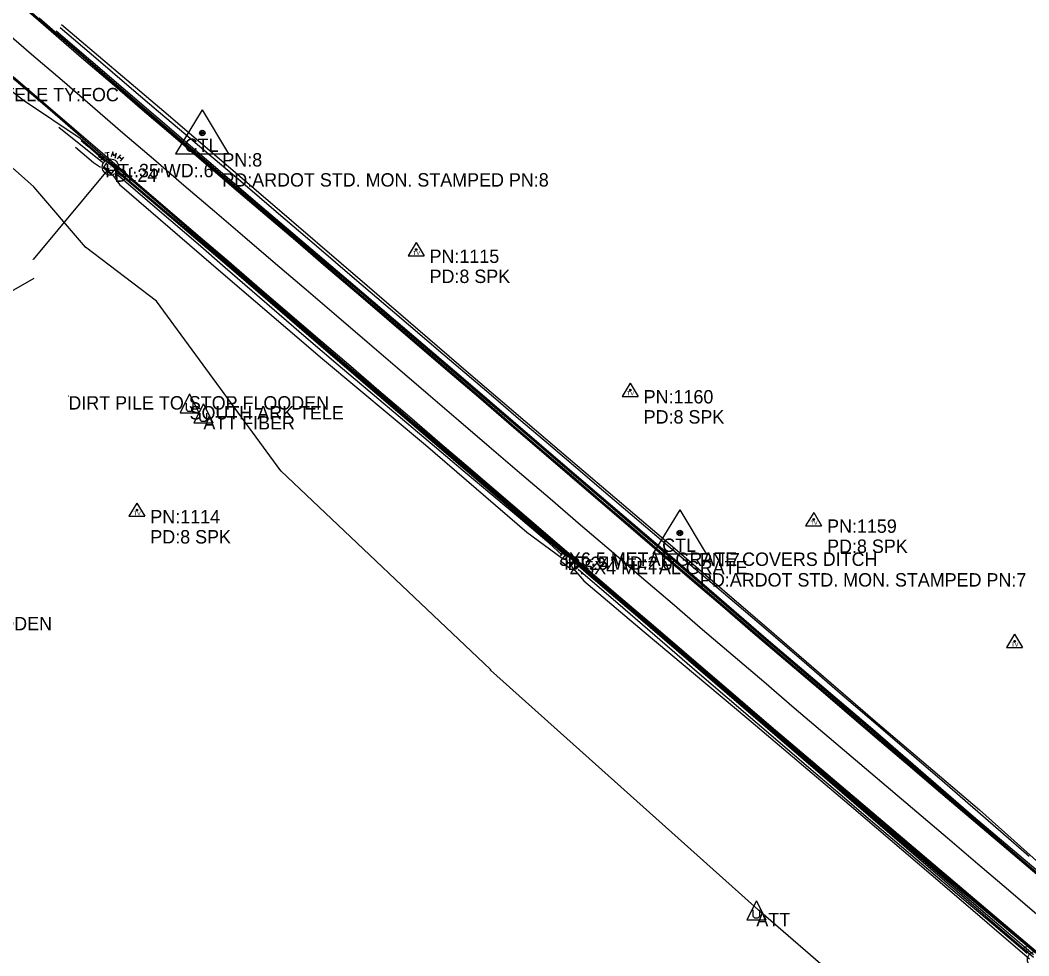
# Model space of a CAD drawing. Extents: x 878399 to 889864, y 1564003 to 1567413.
# Drawn here: x 884308.5 to 884685, y 1565532.7 to 1565882 of the extents above; entities that cross this region are included whole.
import ezdxf

# ---------------------------------------------------------------- set-up
doc = ezdxf.new("R2010")
doc.units = 0
for name, color, linetype in [('S_CATCH_BASIN_ANNOT', 7, 'Continuous'), ('S_DITCHLINE', 7, 'Continuous'), ('S_DRG_PT_SYM', 7, 'Continuous'), ('S_DROP_INLET_ANNOT', 7, 'Continuous'), ('S_EDGE_CONCRETE', 7, 'Continuous'), ('S_EDGE_PAVEMENT', 7, 'Continuous'), ('S_FIBER_OPTIC_CABLE', 7, 'Continuous'), ('S_MSC_PT_SYM', 7, 'Continuous'), ('S_PAVEMENT_CROWN', 7, 'Continuous'), ('S_PRIMARY_CTL', 7, 'Continuous'), ('S_PRIMARY_CTL_ANNOT', 7, 'Continuous'), ('S_SECONDARY_CTL', 7, 'Continuous'), ('S_SECONDARY_CTL_ANNOT', 7, 'Continuous'), ('S_SHOULDER', 7, 'Continuous'), ('S_STORM_SEWER', 7, 'Continuous'), ('S_STORM_SEWER_ANNOT', 7, 'Continuous'), ('S_SURVEY_TEXT_ANNOT', 7, 'Continuous'), ('S_UTILITY_POLE', 7, 'Continuous'), ('S_UTILITY_POLE_ANNOT', 7, 'Continuous'), ('S_UTL_PT_SYM', 7, 'Continuous')]:
    doc.layers.add(name, color=color, linetype=linetype)

msp = doc.modelspace()

# ---------------------------------------------------------------- linework, layer by layer
at = {"layer": 'S_DITCHLINE'}
for points in [[(884685.15, 1565569.81), (884674.64, 1565578.91), (884664.13, 1565588), (884653.63, 1565597.1), (884643.12, 1565606.2), (884628.83, 1565618.48), (884614.53, 1565630.77), (884600.24, 1565643.05), (884585.94, 1565655.34), (884571.02, 1565668.05), (884556.1, 1565680.77), (884541.18, 1565693.48), (884526.26, 1565706.2), (884515.97, 1565714.94), (884505.68, 1565723.69), (884495.4, 1565732.44), (884485.11, 1565741.19), (884466.28, 1565757.28), (884447.44, 1565773.36), (884433.25, 1565785.49), (884419.07, 1565797.62), (884404.88, 1565809.75), (884390.7, 1565821.88), (884380.52, 1565830.51), (884370.34, 1565839.14), (884360.16, 1565847.77), (884349.98, 1565856.41), (884336.68, 1565867.8), (884323.39, 1565879.2)], [(884339.24, 1565828.92), (884322.91, 1565841.99)], [(884510.8, 1565682.24), (884505.96, 1565686.8), (884495.25, 1565695.8), (884484.53, 1565704.79), (884473.82, 1565713.78), (884463.1, 1565722.78), (884451.14, 1565732.92), (884439.18, 1565743.06), (884427.22, 1565753.2), (884415.26, 1565763.35), (884405.17, 1565772.09), (884395.09, 1565780.83), (884385.01, 1565789.58), (884374.93, 1565798.32), (884359.6, 1565811.48), (884344.27, 1565824.65)], [(884313.57, 1565785.57), (884298.88, 1565777.18), (884284.19, 1565768.8), (884269.5, 1565760.41), (884254.81, 1565752.03), (884236.66, 1565741.86), (884218.52, 1565731.69), (884200.38, 1565721.52), (884182.24, 1565711.35), (884162.67, 1565700.67), (884143.1, 1565689.99), (884123.52, 1565679.31), (884103.95, 1565668.64), (884086.69, 1565660), (884069.42, 1565651.36), (884052.15, 1565642.72), (884034.89, 1565634.08)], [(884684.4, 1565533.51), (884671.82, 1565544.18), (884659.24, 1565554.85), (884646.66, 1565565.51), (884634.08, 1565576.18), (884624.26, 1565584.58), (884614.45, 1565592.98), (884604.64, 1565601.38), (884594.82, 1565609.77), (884583.62, 1565619.39), (884572.43, 1565629.01), (884561.23, 1565638.62), (884550.03, 1565648.24), (884533.4, 1565662.59), (884516.78, 1565676.95)]]:
    msp.add_lwpolyline(points, dxfattribs=at)
at = {"layer": 'S_DRG_PT_SYM'}
for points in [[(884340.18, 1565828.36), (884340.18, 1565828.41), (884340.18, 1565828.36), (884340.13, 1565828.36), (884340.18, 1565828.36), (884340.18, 1565828.31), (884340.18, 1565828.36), (884340.23, 1565828.36)], [(884509.62, 1565683.26), (884509.62, 1565683.31), (884509.62, 1565683.26), (884509.57, 1565683.26), (884509.62, 1565683.26), (884509.62, 1565683.21), (884509.62, 1565683.26), (884509.67, 1565683.26)], [(884511.51, 1565681.81), (884511.51, 1565681.86), (884511.51, 1565681.81), (884511.46, 1565681.81), (884511.51, 1565681.81), (884511.51, 1565681.76), (884511.51, 1565681.81), (884511.56, 1565681.81)], [(884513.49, 1565680.14), (884513.49, 1565680.19), (884513.49, 1565680.14), (884513.44, 1565680.14), (884513.49, 1565680.14), (884513.49, 1565680.09), (884513.49, 1565680.14), (884513.54, 1565680.14)]]:
    msp.add_lwpolyline(points, dxfattribs=at)
at = {"layer": 'S_EDGE_CONCRETE'}
for points in [[(884321.95, 1565878.07), (884359.86, 1565845.48), (884397.91, 1565812.97), (884436.05, 1565780.63), (884473.97, 1565748.16), (884511.98, 1565715.58), (884549.99, 1565683.11), (884587.82, 1565650.46), (884625.88, 1565618.07), (884664.43, 1565584.66), (884703.02, 1565551.9)], [(884323.93, 1565880.39), (884362.03, 1565848.01), (884400.08, 1565815.49), (884438.03, 1565782.92), (884475.84, 1565750.35), (884513.92, 1565717.85), (884552.01, 1565685.45), (884589.9, 1565652.9), (884627.72, 1565620.23), (884666.58, 1565587.18), (884704.34, 1565553.44)], [(884331.19, 1565837.05), (884333.69, 1565834.93), (884337.93, 1565831.28), (884340.31, 1565829.21)], [(884329.11, 1565834.63), (884331.61, 1565832.51), (884335.89, 1565828.9), (884338.5, 1565827.11)], [(884344.06, 1565825.6), (884347.53, 1565823.02), (884385.57, 1565790.66), (884423.49, 1565758.06), (884461.52, 1565725.46), (884499.46, 1565692.99), (884511.84, 1565682.36)], [(884342.93, 1565824.29), (884345.52, 1565820.67), (884383.37, 1565788.1), (884421.31, 1565755.54), (884459.79, 1565723.43), (884497.65, 1565690.88), (884510.78, 1565681.13)], [(884514.23, 1565678.05), (884518.85, 1565672.72), (884541.36, 1565653.58), (884579.74, 1565621.54), (884617.9, 1565589.19), (884653.7, 1565558.74), (884685.33, 1565531.53)], [(884515.49, 1565679.51), (884520.78, 1565674.96), (884543.23, 1565655.78), (884581.22, 1565623.28), (884619.31, 1565590.84), (884655, 1565560.28), (884686.74, 1565533.19)]]:
    msp.add_lwpolyline(points, dxfattribs=at)
for points in [[(884344.03, 1565826.49), (884340.96, 1565829.03), (884339.39, 1565827.05), (884342.45, 1565824.52)], [(884342.53, 1565824.71), (884344.23, 1565826.64), (884341.27, 1565829.1), (884339.68, 1565827.32)], [(884512.15, 1565682.46), (884510.24, 1565680.17), (884513.52, 1565677.51), (884515.47, 1565679.77)]]:
    msp.add_lwpolyline(points, close=True, dxfattribs=at)
at = {"layer": 'S_EDGE_PAVEMENT'}
for points in [[(884308.74, 1565887.7), (884320.04, 1565877.9), (884331.41, 1565868.12), (884342.79, 1565858.35), (884354.16, 1565848.57), (884365.56, 1565838.81), (884376.99, 1565829.04), (884388.4, 1565819.3), (884399.81, 1565809.56), (884411.21, 1565799.81), (884422.61, 1565790.07), (884434.02, 1565780.32), (884445.36, 1565770.61), (884456.76, 1565760.85), (884456.76, 1565760.85), (884468.15, 1565751.09), (884479.53, 1565741.32), (884490.9, 1565731.54), (884502.3, 1565721.72), (884513.68, 1565711.95), (884525.07, 1565702.19), (884536.47, 1565692.43), (884547.86, 1565682.67), (884547.86, 1565682.67), (884547.86, 1565682.67), (884559.23, 1565672.93), (884570.62, 1565663.17), (884582.01, 1565653.41), (884582.01, 1565653.41), (884582.01, 1565653.41), (884593.42, 1565643.66), (884604.83, 1565633.93), (884604.83, 1565633.93), (884616.24, 1565624.22), (884627.65, 1565614.49), (884639.07, 1565604.76), (884650.49, 1565595.03), (884661.91, 1565585.29), (884661.91, 1565585.29), (884673.34, 1565575.58), (884684.78, 1565565.87), (884696.21, 1565556.16)], [(884309.18, 1565887.96), (884320.48, 1565878.16), (884331.85, 1565868.38), (884343.23, 1565858.61), (884354.6, 1565848.83), (884365.99, 1565839.08), (884377.43, 1565829.31), (884388.84, 1565819.57), (884400.24, 1565809.82), (884411.65, 1565800.08), (884423.05, 1565790.33), (884434.45, 1565780.59), (884445.8, 1565770.88), (884457.19, 1565761.12), (884457.19, 1565761.12), (884468.58, 1565751.36), (884479.96, 1565741.59), (884491.33, 1565731.81), (884502.73, 1565721.99), (884514.11, 1565712.22), (884525.5, 1565702.46), (884536.89, 1565692.7), (884548.29, 1565682.94), (884548.29, 1565682.94), (884548.29, 1565682.94), (884559.66, 1565673.2), (884571.04, 1565663.44), (884582.43, 1565653.68), (884582.43, 1565653.68), (884582.43, 1565653.68), (884593.84, 1565643.94), (884605.26, 1565634.21), (884605.26, 1565634.21), (884616.66, 1565624.49), (884628.08, 1565614.77), (884639.49, 1565605.04), (884650.91, 1565595.31), (884662.33, 1565585.57), (884662.33, 1565585.57), (884673.76, 1565575.86), (884685.2, 1565566.15)], [(884305.36, 1565860.75), (884316.73, 1565850.97), (884328.11, 1565841.19), (884339.48, 1565831.41), (884350.85, 1565821.62), (884362.2, 1565811.9), (884373.6, 1565802.15), (884384.99, 1565792.39), (884396.37, 1565782.62), (884407.75, 1565772.84), (884419.13, 1565763.06), (884430.57, 1565753.24), (884430.57, 1565753.24), (884430.57, 1565753.24), (884441.96, 1565743.48), (884441.96, 1565743.48), (884441.96, 1565743.48), (884453.35, 1565733.72), (884464.74, 1565723.96), (884476.13, 1565714.2), (884487.49, 1565704.48), (884498.88, 1565694.73), (884510.27, 1565684.96), (884510.27, 1565684.96), (884510.27, 1565684.96), (884521.65, 1565675.19), (884533.06, 1565665.45), (884544.49, 1565655.68), (884555.87, 1565645.91), (884555.87, 1565645.91), (884555.87, 1565645.91), (884567.26, 1565636.14), (884578.64, 1565626.38), (884590.07, 1565616.65), (884601.52, 1565606.93), (884612.96, 1565597.22), (884624.4, 1565587.52), (884635.83, 1565577.81), (884647.26, 1565568.1), (884658.7, 1565558.4), (884670.15, 1565548.71), (884681.61, 1565539.03), (884693.05, 1565529.33)], [(884305.8, 1565861.01), (884317.17, 1565851.23), (884328.55, 1565841.46), (884339.92, 1565831.68), (884351.28, 1565821.89), (884362.64, 1565812.17), (884374.03, 1565802.41), (884385.43, 1565792.66), (884396.81, 1565782.88), (884408.18, 1565773.11), (884419.56, 1565763.33), (884431, 1565753.51), (884431, 1565753.51), (884431, 1565753.51), (884442.39, 1565743.75), (884442.39, 1565743.75), (884442.39, 1565743.75), (884453.78, 1565733.98), (884465.17, 1565724.22), (884476.56, 1565714.47), (884487.92, 1565704.75), (884499.31, 1565695), (884510.7, 1565685.23), (884510.7, 1565685.23), (884510.7, 1565685.23), (884522.08, 1565675.46), (884533.48, 1565665.72), (884544.92, 1565655.95), (884556.3, 1565646.18), (884556.3, 1565646.18), (884556.3, 1565646.18), (884567.69, 1565636.42), (884579.07, 1565626.65), (884590.49, 1565616.93), (884601.95, 1565607.2), (884613.39, 1565597.5), (884624.82, 1565587.79), (884636.26, 1565578.08), (884647.68, 1565568.38), (884659.12, 1565558.68), (884670.57, 1565548.99), (884682.03, 1565539.31), (884693.47, 1565529.6)]]:
    msp.add_lwpolyline(points, dxfattribs=at)
at = {"layer": 'S_FIBER_OPTIC_CABLE'}
for p, q in [((884313.56, 1565819.73), (884254.77, 1565872.1)), ((884332.82, 1565797.2), (884313.56, 1565819.73)), ((884359.4, 1565777.11), (884332.82, 1565797.2)), ((884405.75, 1565713.8), (884359.4, 1565777.11)), ((884484.08, 1565639.63), (884405.75, 1565713.8)), ((884484.1, 1565639.3), (884484.08, 1565639.63)), ((884585.04, 1565548.94), (884484.1, 1565639.3)), ((884630.03, 1565510.1), (884585.04, 1565548.94))]:
    msp.add_line(p, q, dxfattribs=at)
at = {"layer": 'S_MSC_PT_SYM'}
msp.add_lwpolyline([(884326.45, 1565741.62), (884326.45, 1565741.67), (884326.45, 1565741.62), (884326.4, 1565741.62), (884326.45, 1565741.62), (884326.45, 1565741.57), (884326.45, 1565741.62), (884326.5, 1565741.62)], dxfattribs=at)
at = {"layer": 'S_PAVEMENT_CROWN'}
msp.add_lwpolyline([(884301.35, 1565879.14), (884312.72, 1565869.34), (884312.72, 1565869.34), (884324.08, 1565859.55), (884335.44, 1565849.75), (884335.44, 1565849.75), (884335.44, 1565849.75), (884346.81, 1565839.98), (884358.2, 1565830.22), (884369.59, 1565820.46), (884380.99, 1565810.71), (884380.99, 1565810.71), (884380.99, 1565810.71), (884392.38, 1565800.95), (884403.78, 1565791.2), (884415.17, 1565781.44), (884426.57, 1565771.69), (884437.96, 1565761.92), (884449.36, 1565752.16), (884460.75, 1565742.4), (884472.14, 1565732.64), (884472.14, 1565732.64), (884483.53, 1565722.88), (884494.92, 1565713.13), (884494.92, 1565713.13), (884494.92, 1565713.13), (884506.31, 1565703.37), (884517.7, 1565693.6), (884529.09, 1565683.84), (884529.09, 1565683.84), (884529.09, 1565683.84), (884540.47, 1565674.07), (884551.85, 1565664.29), (884563.22, 1565654.51), (884574.62, 1565644.76), (884574.62, 1565644.76), (884586.04, 1565635.03), (884597.46, 1565625.3), (884597.46, 1565625.3), (884597.46, 1565625.3), (884608.88, 1565615.58), (884608.88, 1565615.58), (884608.88, 1565615.58), (884620.33, 1565605.88), (884631.77, 1565596.17), (884643.21, 1565586.47), (884654.62, 1565576.74), (884654.62, 1565576.74), (884666.03, 1565567), (884677.44, 1565557.27), (884688.85, 1565547.53)], dxfattribs=at)
at = {"layer": 'S_PRIMARY_CTL'}
for p, q in [((884376.44, 1565848.57), (884366.4, 1565832.06)), ((884376.44, 1565848.57), (884386.26, 1565832.06)), ((884366.4, 1565832.06), (884386.26, 1565832.06)), ((884554.74, 1565699.24), (884544.71, 1565682.72)), ((884554.74, 1565699.24), (884564.56, 1565682.72)), ((884544.71, 1565682.72), (884564.56, 1565682.72))]:
    msp.add_line(p, q, dxfattribs=at)
for centre, radius in [((884376.44, 1565839.87), 1.04), ((884376.44, 1565839.87), 0.609), ((884376.44, 1565839.87), 0.344), ((884554.74, 1565690.54), 1.04), ((884554.74, 1565690.54), 0.609), ((884554.74, 1565690.54), 0.344)]:
    msp.add_circle(centre, radius, dxfattribs=at)
at = {"layer": 'S_SECONDARY_CTL'}
for p, q in [((884456.3, 1565798.98), (884453.29, 1565794.02)), ((884456.3, 1565798.98), (884459.25, 1565794.02)), ((884453.29, 1565794.02), (884459.25, 1565794.02)), ((884536.23, 1565746.51), (884533.22, 1565741.55)), ((884536.23, 1565746.51), (884539.18, 1565741.55)), ((884533.22, 1565741.55), (884539.18, 1565741.55)), ((884352.05, 1565701.73), (884349.04, 1565696.78)), ((884352.05, 1565701.73), (884355, 1565696.78)), ((884349.04, 1565696.78), (884355, 1565696.78)), ((884604.72, 1565698.21), (884601.71, 1565693.26)), ((884604.72, 1565698.21), (884607.67, 1565693.26)), ((884601.71, 1565693.26), (884607.67, 1565693.26)), ((884679.72, 1565652.75), (884676.71, 1565647.8)), ((884679.72, 1565652.75), (884682.67, 1565647.8)), ((884676.71, 1565647.8), (884682.67, 1565647.8))]:
    msp.add_line(p, q, dxfattribs=at)
for centre, radius in [((884456.3, 1565796.37), 0.311), ((884456.3, 1565796.37), 0.183), ((884456.3, 1565796.37), 0.103), ((884536.23, 1565743.9), 0.311), ((884536.23, 1565743.9), 0.183), ((884536.23, 1565743.9), 0.103), ((884352.05, 1565699.12), 0.311), ((884352.05, 1565699.12), 0.183), ((884352.05, 1565699.12), 0.103), ((884604.72, 1565695.6), 0.311), ((884604.72, 1565695.6), 0.183), ((884604.72, 1565695.6), 0.103), ((884679.72, 1565650.14), 0.311), ((884679.72, 1565650.14), 0.183), ((884679.72, 1565650.14), 0.103)]:
    msp.add_circle(centre, radius, dxfattribs=at)
at = {"layer": 'S_SHOULDER'}
for points in [[(884270.03, 1565882.19), (884310.06, 1565851.92), (884330.8, 1565837.96), (884344.52, 1565826.15), (884347.79, 1565823.32), (884385.89, 1565791.03), (884423.82, 1565758.45), (884461.85, 1565725.85), (884499.85, 1565693.44), (884512.13, 1565682.71), (884515.64, 1565679.69), (884520.93, 1565675.14), (884543.39, 1565655.96), (884581.35, 1565623.43), (884619.55, 1565591.12), (884655.38, 1565560.72), (884687.38, 1565533.95)], [(884315.55, 1565882.9), (884321.54, 1565877.6), (884359.45, 1565845), (884397.59, 1565812.6), (884435.73, 1565780.26), (884473.65, 1565747.79), (884511.66, 1565715.22), (884549.66, 1565682.72), (884587.52, 1565650.1), (884625.56, 1565617.69), (884664.18, 1565584.36), (884702.58, 1565551.39), (884704.78, 1565549.31), (884722.81, 1565534.04), (884741.48, 1565517.97), (884779.63, 1565485.61), (884817.88, 1565453.42), (884855.77, 1565420.91), (884891.75, 1565389.81), (884929.91, 1565357.22)]]:
    msp.add_lwpolyline(points, dxfattribs=at)
at = {"layer": 'S_STORM_SEWER'}
for p, q in [((884340.12, 1565832.44), (884341.63, 1565832.71)), ((884340.89, 1565832.59), (884341.24, 1565830.65)), ((884337.83, 1565831.47), (884337.75, 1565831.08)), ((884337.75, 1565831.08), (884337.95, 1565830.81)), ((884338.37, 1565831.86), (884337.83, 1565831.47)), ((884337.95, 1565830.81), (884338.37, 1565830.69)), ((884338.8, 1565831.78), (884338.37, 1565831.86)), ((884338.37, 1565830.69), (884338.91, 1565831.04)), ((884338.91, 1565829.88), (884338.53, 1565829.96)), ((884338.91, 1565831.04), (884339.38, 1565830.96)), ((884339.46, 1565830.27), (884338.91, 1565829.88)), ((884339.38, 1565830.96), (884339.53, 1565830.69)), ((884339.53, 1565830.69), (884339.46, 1565830.27)), ((884344.8, 1565830.23), (884346.04, 1565831.7)), ((884345.46, 1565831), (884346.43, 1565830.19)), ((884347.01, 1565830.89), (884345.77, 1565829.41)), ((884341.58, 1565826.62), (884313.31, 1565792.71)), ((884512.82, 1565681.71), (884343.64, 1565826.64)), ((884686.78, 1565532.07), (884514.98, 1565679.93)), ((884683.21, 1565535.56), (884683.14, 1565535.17)), ((884683.14, 1565535.17), (884683.33, 1565534.9)), ((884683.76, 1565535.95), (884683.21, 1565535.56)), ((884683.33, 1565534.9), (884683.76, 1565534.78)), ((884684.18, 1565535.87), (884683.76, 1565535.95)), ((884683.76, 1565534.78), (884684.3, 1565535.13)), ((884684.3, 1565535.13), (884684.76, 1565535.05)), ((884684.76, 1565535.05), (884684.92, 1565534.78)), ((884684.92, 1565534.78), (884684.84, 1565534.36)), ((884684.3, 1565533.97), (884683.91, 1565534.05)), ((884684.84, 1565534.36), (884684.3, 1565533.97))]:
    msp.add_line(p, q, dxfattribs=at)
msp.add_lwpolyline([(884343.91, 1565830.54), (884344.46, 1565832.4), (884343.41, 1565831.39), (884343.02, 1565832.82), (884342.48, 1565830.96)], dxfattribs=at)
for centre in [(884342.16, 1565827.17), (884687.54, 1565531.25)]:
    msp.add_circle(centre, 3.05, dxfattribs=at)
at = {"layer": 'S_UTILITY_POLE'}
for p, q in [((884371.7, 1565742.46), (884368.17, 1565735.37)), ((884371.7, 1565742.46), (884375.19, 1565735.37)), ((884370.5, 1565736.61), (884370.5, 1565739.05)), ((884372.86, 1565739.05), (884372.86, 1565736.61)), ((884376.87, 1565738.71), (884373.34, 1565731.62)), ((884376.87, 1565738.71), (884380.36, 1565731.62)), ((884368.17, 1565735.37), (884375.19, 1565735.37)), ((884371.12, 1565735.95), (884370.5, 1565736.61)), ((884372.32, 1565735.95), (884371.12, 1565735.95)), ((884372.86, 1565736.61), (884372.32, 1565735.95)), ((884375.67, 1565732.86), (884375.67, 1565735.3)), ((884378.03, 1565735.3), (884378.03, 1565732.86)), ((884373.34, 1565731.62), (884380.36, 1565731.62)), ((884376.29, 1565732.2), (884375.67, 1565732.86)), ((884377.49, 1565732.2), (884376.29, 1565732.2)), ((884378.03, 1565732.86), (884377.49, 1565732.2)), ((884583.3, 1565553.24), (884579.77, 1565546.14)), ((884582.1, 1565547.38), (884582.1, 1565549.83)), ((884583.3, 1565553.24), (884586.79, 1565546.14)), ((884584.46, 1565549.83), (884584.46, 1565547.38)), ((884579.77, 1565546.14), (884586.79, 1565546.14)), ((884582.72, 1565546.73), (884582.1, 1565547.38)), ((884583.92, 1565546.73), (884582.72, 1565546.73)), ((884584.46, 1565547.38), (884583.92, 1565546.73))]:
    msp.add_line(p, q, dxfattribs=at)
at = {"layer": 'S_UTL_PT_SYM'}
for points in [[(884341.58, 1565826.62), (884341.58, 1565826.67), (884341.58, 1565826.62), (884341.53, 1565826.62), (884341.58, 1565826.62), (884341.58, 1565826.57), (884341.58, 1565826.62), (884341.63, 1565826.62)], [(884342.17, 1565827.17), (884342.17, 1565827.22), (884342.17, 1565827.17), (884342.12, 1565827.17), (884342.17, 1565827.17), (884342.17, 1565827.12), (884342.17, 1565827.17), (884342.22, 1565827.17)], [(884343.64, 1565826.64), (884343.64, 1565826.69), (884343.64, 1565826.64), (884343.59, 1565826.64), (884343.64, 1565826.64), (884343.64, 1565826.59), (884343.64, 1565826.64), (884343.69, 1565826.64)], [(884313.56, 1565819.73), (884313.56, 1565819.78), (884313.56, 1565819.73), (884313.51, 1565819.73), (884313.56, 1565819.73), (884313.56, 1565819.68), (884313.56, 1565819.73), (884313.61, 1565819.73)], [(884332.82, 1565797.2), (884332.82, 1565797.25), (884332.82, 1565797.2), (884332.77, 1565797.2), (884332.82, 1565797.2), (884332.82, 1565797.15), (884332.82, 1565797.2), (884332.87, 1565797.2)], [(884313.31, 1565792.71), (884313.31, 1565792.76), (884313.31, 1565792.71), (884313.26, 1565792.71), (884313.31, 1565792.71), (884313.31, 1565792.66), (884313.31, 1565792.71), (884313.36, 1565792.71)], [(884359.4, 1565777.11), (884359.4, 1565777.16), (884359.4, 1565777.11), (884359.35, 1565777.11), (884359.4, 1565777.11), (884359.4, 1565777.06), (884359.4, 1565777.11), (884359.45, 1565777.11)], [(884405.75, 1565713.8), (884405.75, 1565713.85), (884405.75, 1565713.8), (884405.7, 1565713.8), (884405.75, 1565713.8), (884405.75, 1565713.75), (884405.75, 1565713.8), (884405.8, 1565713.8)], [(884512.82, 1565681.71), (884512.82, 1565681.76), (884512.82, 1565681.71), (884512.77, 1565681.71), (884512.82, 1565681.71), (884512.82, 1565681.66), (884512.82, 1565681.71), (884512.87, 1565681.71)], [(884513.42, 1565680.43), (884513.42, 1565680.48), (884513.42, 1565680.43), (884513.37, 1565680.43), (884513.42, 1565680.43), (884513.42, 1565680.38), (884513.42, 1565680.43), (884513.47, 1565680.43)], [(884514.98, 1565679.93), (884514.98, 1565679.98), (884514.98, 1565679.93), (884514.93, 1565679.93), (884514.98, 1565679.93), (884514.98, 1565679.88), (884514.98, 1565679.93), (884515.03, 1565679.93)], [(884484.08, 1565639.63), (884484.08, 1565639.68), (884484.08, 1565639.63), (884484.03, 1565639.63), (884484.08, 1565639.63), (884484.08, 1565639.58), (884484.08, 1565639.63), (884484.13, 1565639.63)], [(884484.1, 1565639.3), (884484.1, 1565639.35), (884484.1, 1565639.3), (884484.05, 1565639.3), (884484.1, 1565639.3), (884484.1, 1565639.25), (884484.1, 1565639.3), (884484.15, 1565639.3)], [(884585.04, 1565548.94), (884585.04, 1565548.99), (884585.04, 1565548.94), (884584.99, 1565548.94), (884585.04, 1565548.94), (884585.04, 1565548.89), (884585.04, 1565548.94), (884585.09, 1565548.94)]]:
    msp.add_lwpolyline(points, dxfattribs=at)

# ---------------------------------------------------------------- texts
at = {"layer": 'S_CATCH_BASIN_ANNOT'}
for s, p in [('HT:.35 WD:.6', (884340.18, 1565823.36)), ('HT:.5 WD:2.0', (884511.51, 1565676.81))]:
    msp.add_text(s, height=5, dxfattribs=at).set_placement(p)
at = {"layer": 'S_DROP_INLET_ANNOT'}
for s, p in [('3X6.5 METAL GRATE COVERS DITCH', (884509.62, 1565678.26)), ('2.5X4 METAL GRATE', (884513.49, 1565675.14))]:
    msp.add_text(s, height=5, dxfattribs=at).set_placement(p)
at = {"layer": 'S_PRIMARY_CTL'}
for p in [(884369.85, 1565832.8), (884548.15, 1565683.46)]:
    msp.add_text('CTL', height=5, rotation=360, dxfattribs=at).set_placement(p)
at = {"layer": 'S_PRIMARY_CTL_ANNOT'}
for s, p in [('PN:8', (884383.94, 1565827.37)), ('PD:ARDOT STD. MON. STAMPED PN:8', (884383.94, 1565819.87)), ('PN:7', (884562.24, 1565678.04)), ('PD:ARDOT STD. MON. STAMPED PN:7', (884562.24, 1565670.54))]:
    msp.add_text(s, height=5, dxfattribs=at).set_placement(p)
at = {"layer": 'S_SECONDARY_CTL'}
for p in [(884455.1, 1565794.36), (884535.03, 1565741.89), (884350.84, 1565697.11), (884603.52, 1565693.59), (884678.52, 1565648.13)]:
    msp.add_text('TV', height=1.5, rotation=360, dxfattribs=at).set_placement(p)
at = {"layer": 'S_SECONDARY_CTL_ANNOT'}
for s, p in [('PN:1115', (884461.3, 1565791.37)), ('PD:8 SPK', (884461.3, 1565783.87)), ('PN:1160', (884541.23, 1565738.9)), ('PD:8 SPK', (884541.23, 1565731.4)), ('PN:1114', (884357.05, 1565694.12)), ('PN:1159', (884609.72, 1565690.6)), ('PD:8 SPK', (884357.05, 1565686.62)), ('PD:8 SPK', (884609.72, 1565683.1))]:
    msp.add_text(s, height=5, dxfattribs=at).set_placement(p)
at = {"layer": 'S_STORM_SEWER_ANNOT'}
for p in [(884343.64, 1565821.64), (884512.82, 1565676.71)]:
    msp.add_text('DI:24"', height=5, dxfattribs=at).set_placement(p)
at = {"layer": 'S_SURVEY_TEXT_ANNOT'}
for p in [(884326.45, 1565736.62), (884222.99, 1565654.21)]:
    msp.add_text('DIRT PILE TO STOP FLOODEN', height=5, dxfattribs=at).set_placement(p)
at = {"layer": 'S_UTILITY_POLE_ANNOT'}
for s, p in [('SOUTH ARK TELE TY:FOC', (884261.32, 1565851.71)), ('SOUTH ARK TELE', (884371.7, 1565732.93)), ('ATT FIBER', (884376.87, 1565729.18)), ('ATT', (884583.3, 1565543.7))]:
    msp.add_text(s, height=5, dxfattribs=at).set_placement(p)

doc.saveas('drawing.dxf')
